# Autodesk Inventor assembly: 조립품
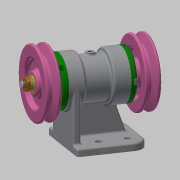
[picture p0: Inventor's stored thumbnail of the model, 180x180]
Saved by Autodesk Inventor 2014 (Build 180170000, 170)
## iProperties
Created: 2020-06
Part Number: 조립품
Document SubType Name: Assembly
Designer: kh
Author: kh
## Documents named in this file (12)
- C:\Users\kh\Desktop\700606V1029\조립품.iam
- C:\Users\kh\Desktop\700606V1029\본체.ipt
- C:\Users\kh\Desktop\700606V1029\V-벨트풀리.ipt
- C:\Users\kh\Desktop\700606V1029\너트 M10.ipt
- C:\Users\kh\Desktop\700606V1029\베어링 6204.ipt
- C:\Users\kh\Desktop\700606V1029\볼트 M4.ipt
- C:\Users\kh\Desktop\700606V1029\스프링 와셔 10.ipt
- C:\Users\kh\Desktop\700606V1029\오일 실 20 32 5.ipt
- C:\Users\kh\Desktop\700606V1029\축.ipt
- C:\Users\kh\Desktop\700606V1029\커버.ipt
- C:\Users\kh\Desktop\700606V1029\키 5x5x12.ipt
- C:\Users\kh\Desktop\700606V1029\평면 와셔 10x21.ipt
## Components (2 placed, 1 different names)
1. V-벨트풀리:1 — Mate:35, Mate:36, Angle:2
2. V-벨트풀리:2 — Mate:37, Angle:3, Mate:38
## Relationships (6: Mate 4, Angle 2)
- Mate:35: V-벨트풀리:1
- Mate:36: V-벨트풀리:1
- Angle:2: V-벨트풀리:1
- Mate:37: V-벨트풀리:2
- Angle:3: V-벨트풀리:2
- Mate:38: V-벨트풀리:2
